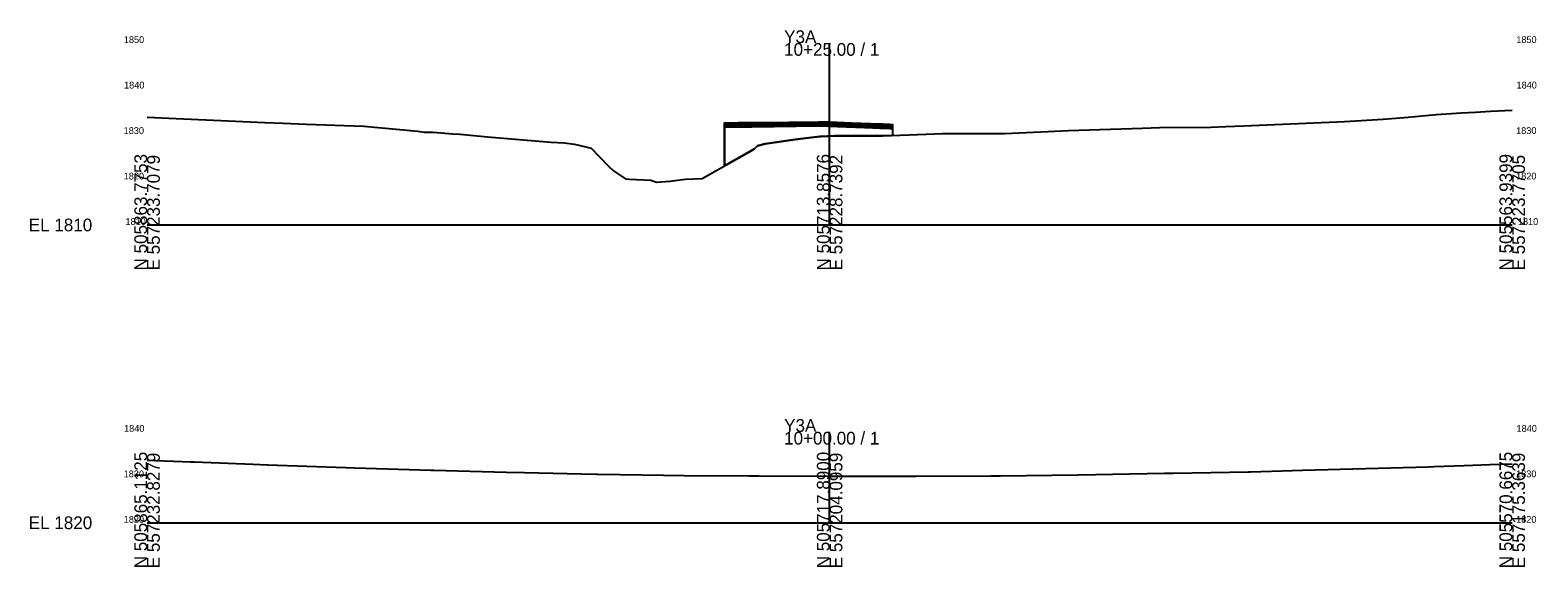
# Model space of a CAD drawing. Extents: x -26 to 306, y -102 to 258.
# Drawn here: x -25.7 to 305.6, y -101.5 to 16.5 of the extents above; entities that cross this region are included whole.
import ezdxf

# ---------------------------------------------------------------- set-up
doc = ezdxf.new("R2010")
doc.units = 0
for name, color, linetype in [('Default', 7, 'Continuous'), ('Exist Cross Section Cell', 7, 'Continuous'), ('Exist XS Ground Line', 7, 'Continuous'), ('Prop CMT Pvmt Course 1', 7, 'Continuous'), ('Prop CMT Pvmt Course 2', 7, 'Continuous'), ('Prop CMT Pvmt Course 3', 7, 'Continuous'), ('Prop CMT Pvmt Course 4', 7, 'Continuous'), ('Prop XS Elevation Labels', 7, 'Continuous'), ('Prop XS Finish Grade', 7, 'Continuous'), ('Scratch_Level_1', 7, 'Continuous'), ('Scratch_Level_9', 7, 'Continuous')]:
    doc.layers.add(name, color=color, linetype=linetype)

msp = doc.modelspace()

# ---------------------------------------------------------------- linework, layer by layer
at = {"layer": 'Exist Cross Section Cell'}
for p, q in [((150, -26.34), (150, 13.66)), ((0, -26.34), (150, -26.34)), ((150, -26.34), (300, -26.34)), ((150, -91.82), (150, -71.82)), ((0, -91.82), (150, -91.82)), ((150, -91.82), (300, -91.82))]:
    msp.add_line(p, q, dxfattribs=at)
at = {"layer": 'Exist XS Ground Line'}
for points in [[(0, -2.61), (6.38, -2.92), (14.6, -3.3), (25.87, -3.8), (29.91, -3.96), (35, -4.17), (47.62, -4.61), (59.47, -5.71), (60.94, -5.91), (61.99, -5.92), (62.9, -5.94), (67.19, -6.27), (68.75, -6.38), (71.06, -6.63), (74.84, -6.97), (88.8, -8.1), (91.69, -8.31), (93.94, -8.58), (96.39, -9.15), (97.58, -9.45), (101.37, -13.44), (102.53, -14.41), (105.16, -16.22), (106.05, -16.26), (110.72, -16.51), (111.92, -16.92), (114.85, -16.68), (118.29, -16.29), (121.98, -16.11), (132.37, -10.27), (133.52, -9.6), (134.14, -8.96), (135.84, -8.48), (142.41, -7.55), (144.7, -7.22), (147.83, -6.87), (148.15, -6.86), (151.04, -6.76), (159.15, -6.71), (161.67, -6.71), (163.57, -6.67), (173.12, -6.3), (174.8, -6.26), (175.65, -6.26), (188.41, -6.21), (198.05, -5.78), (202.47, -5.58), (207.07, -5.42), (218.72, -5.06), (222.51, -4.94), (233.8, -4.82), (237.07, -4.69), (241.02, -4.52), (263.13, -3.57), (271.62, -3.07), (277.11, -2.65), (283.26, -2.03), (288.84, -1.68), (291.91, -1.53), (295.26, -1.35), (300, -1.11)], [(0, -78.02), (9.65, -78.42), (10.35, -78.44), (23.31, -78.92), (26.47, -79.05), (26.54, -79.05), (43.66, -79.65), (45.65, -79.72), (62.39, -80.25), (63.03, -80.26), (78.93, -80.7), (82.95, -80.8), (98.63, -81.13), (99.15, -81.14), (113.52, -81.34), (118.03, -81.39), (132.31, -81.51), (134.43, -81.52), (149.98, -81.59), (153.11, -81.59), (168.95, -81.6), (185.39, -81.52), (187.53, -81.51), (204.56, -81.29), (204.61, -81.29), (223.62, -80.93), (223.9, -80.93), (225.48, -80.9), (242.03, -80.62), (242.47, -80.61), (251.65, -80.35), (253.92, -80.29), (281.6, -79.53), (282.84, -79.48), (289.48, -79.25), (295.08, -79.03), (300, -78.86)]]:
    msp.add_lwpolyline(points, dxfattribs=at)
at = {"layer": 'Prop CMT Pvmt Course 1'}
msp.add_lwpolyline([(163.24, -4.2), (163.84, -4.22), (163.84, -4.47), (163.24, -4.45), (161.69, -4.39), (161.06, -4.36), (154.79, -4.11), (149.99, -3.92), (149.24, -3.91), (148.39, -3.9), (147.52, -3.89), (134.47, -4.06), (132.9, -4.09), (131.71, -4.05), (129.91, -4.09), (127.14, -4.11), (126.97, -4.11), (126.87, -4.11), (126.87, -3.86), (126.97, -3.86), (127.14, -3.86), (129.91, -3.84), (131.71, -3.8), (132.9, -3.84), (134.47, -3.81), (147.52, -3.64), (148.39, -3.65), (149.24, -3.66), (149.99, -3.67), (154.79, -3.86), (161.06, -4.11), (161.69, -4.14), (163.24, -4.2)], dxfattribs=at)
at = {"layer": 'Prop CMT Pvmt Course 2'}
msp.add_lwpolyline([(163.24, -4.45), (163.84, -4.47), (163.84, -4.8), (163.24, -4.78), (161.69, -4.72), (161.06, -4.69), (154.79, -4.44), (149.99, -4.26), (149.24, -4.25), (148.39, -4.24), (147.52, -4.22), (134.47, -4.39), (132.9, -4.42), (131.71, -4.38), (129.91, -4.42), (127.14, -4.45), (126.97, -4.44), (126.87, -4.45), (126.87, -4.11), (126.97, -4.11), (127.14, -4.11), (129.91, -4.09), (131.71, -4.05), (132.9, -4.09), (134.47, -4.06), (147.52, -3.89), (148.39, -3.9), (149.24, -3.91), (149.99, -3.92), (154.79, -4.11), (161.06, -4.36), (161.69, -4.39), (163.24, -4.45)], dxfattribs=at)
at = {"layer": 'Prop CMT Pvmt Course 3'}
msp.add_lwpolyline([(163.24, -4.78), (163.84, -4.8), (163.84, -5.14), (163.24, -5.11), (161.69, -5.05), (161.06, -5.03), (154.79, -4.78), (149.99, -4.59), (149.24, -4.58), (148.39, -4.57), (147.52, -4.56), (134.47, -4.72), (132.9, -4.75), (131.71, -4.72), (129.91, -4.75), (127.14, -4.78), (126.97, -4.77), (126.87, -4.78), (126.87, -4.45), (126.97, -4.44), (127.14, -4.45), (129.91, -4.42), (131.71, -4.38), (132.9, -4.42), (134.47, -4.39), (147.52, -4.22), (148.39, -4.24), (149.24, -4.25), (149.99, -4.26), (154.79, -4.44), (161.06, -4.69), (161.69, -4.72), (163.24, -4.78)], dxfattribs=at)
at = {"layer": 'Prop CMT Pvmt Course 4'}
for p, q in [((126.87, -4.78), (126.86, -13.37)), ((163.84, -5.14), (163.84, -6.66))]:
    msp.add_line(p, q, dxfattribs=at)
msp.add_lwpolyline([(126.87, -4.78), (126.97, -4.77), (127.14, -4.78), (129.91, -4.75), (131.71, -4.72), (132.9, -4.75), (134.47, -4.72), (147.52, -4.56), (148.39, -4.57), (149.24, -4.58), (149.99, -4.59), (154.79, -4.78), (161.06, -5.03), (161.69, -5.05), (163.24, -5.11), (163.84, -5.14)], dxfattribs=at)
at = {"layer": 'Prop XS Finish Grade'}
msp.add_lwpolyline([(126.87, -3.86), (126.97, -3.86), (127.14, -3.86), (129.91, -3.84), (131.71, -3.8), (132.9, -3.84), (134.47, -3.81), (147.52, -3.64), (148.39, -3.65), (149.24, -3.66), (149.99, -3.67), (154.79, -3.86), (161.06, -4.11), (161.69, -4.14), (163.24, -4.2), (163.84, -4.22)], dxfattribs=at)
at = {"layer": 'Scratch_Level_1'}
msp.add_lwpolyline([(126.87, -4.78), (132.9, -4.75), (147.52, -4.56), (163.84, -5.14), (163.84, -6.66), (159.15, -6.71), (151.04, -6.76), (147.83, -6.87), (142.41, -7.55), (135.84, -8.48), (134.14, -8.96), (133.52, -9.6), (126.86, -13.37)], close=True, dxfattribs=at)
at = {"layer": 'Scratch_Level_9'}
for points in [[(126.87, -3.86), (126.87, -4.11)], [(163.84, -4.22), (163.84, -4.47)]]:
    msp.add_lwpolyline(points, dxfattribs=at)

# ---------------------------------------------------------------- texts
at = {"layer": 'Default'}
for s, height, p in [('X', 0.0025, (178.06, -3.14)), ('X', 0.0025, (122.4, -3.71)), ('X', 0.0025, (126.86, -3.87)), ('X', 0.0025, (163.84, -4.22)), ('X', 0.0025, (166.08, -4.3)), ('-', 0.0001, (0, -26.34)), ('-', 0.0001, (0, -91.82))]:
    msp.add_text(s, height=height, dxfattribs=at).set_placement(p)
at = {"layer": 'Exist Cross Section Cell'}
for s, p in [('Y3A', (140, 13.66)), ('10+25.00 / 1', (140, 10.86)), ('EL 1810', (-26, -27.74)), ('Y3A', (140, -71.82)), ('10+00.00 / 1', (140, -74.62)), ('EL 1820', (-26, -93.22))]:
    msp.add_text(s, height=2.8, dxfattribs=at).set_placement(p)
for s, p in [('N 505863.7753', (0, -36.34)), ('E 557233.7079', (2.8, -36.34)), ('N 505713.8576', (150, -36.34)), ('E 557228.7392', (152.8, -36.34)), ('N 505563.9399', (300, -36.34)), ('E 557223.7705', (302.8, -36.34)), ('N 505865.1125', (0, -101.82)), ('E 557232.8279', (2.8, -101.82)), ('N 505717.8900', (150, -101.82)), ('E 557204.0959', (152.8, -101.82)), ('N 505570.6675', (300, -101.82)), ('E 557175.3639', (302.8, -101.82))]:
    msp.add_text(s, height=2.8, rotation=90, dxfattribs=at).set_placement(p)
at = {"layer": 'Prop XS Elevation Labels'}
for s, p in [('1850', (-5.1, 13.66)), ('1850', (300.9, 13.66)), ('1840', (-5.05, 3.66)), ('1840', (300.95, 3.66)), ('1830', (-5.14, -6.34)), ('1830', (300.86, -6.34)), ('1820', (-5.13, -16.34)), ('1820', (300.87, -16.34)), ('1810', (-4.75, -26.34)), ('1810', (301.25, -26.34)), ('1840', (-5.05, -71.82)), ('1840', (300.95, -71.82)), ('1830', (-5.14, -81.82)), ('1830', (300.86, -81.82)), ('1820', (-5.13, -91.82)), ('1820', (300.87, -91.82))]:
    msp.add_text(s, height=1.5, dxfattribs=at).set_placement(p)

doc.saveas('drawing.dxf')
